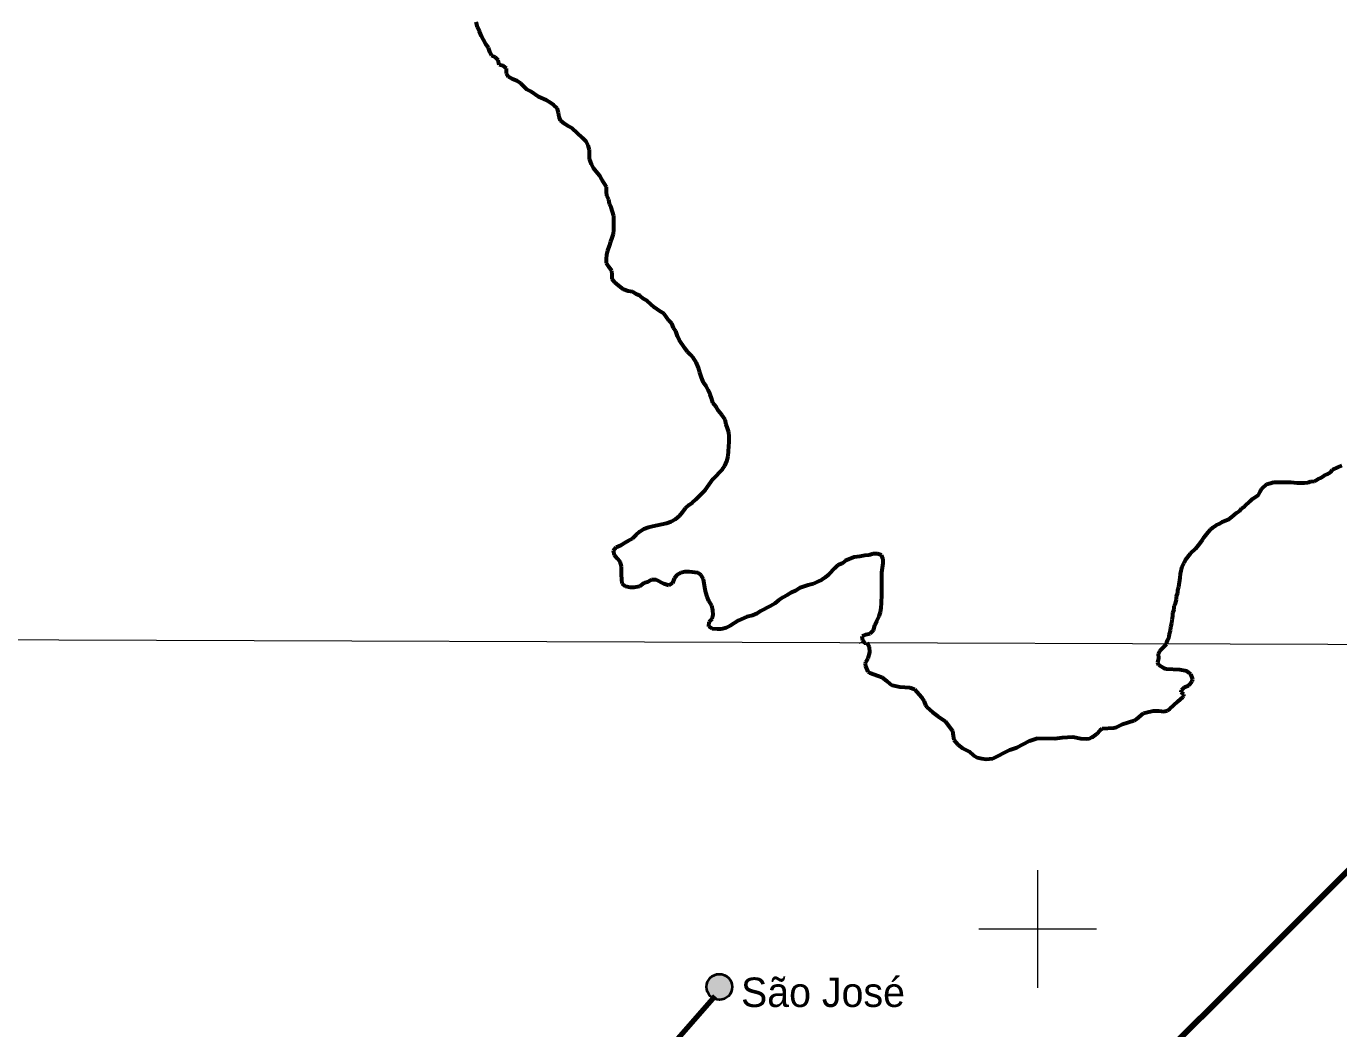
# Model space of a CAD drawing. Extents: x 553962 to 842807, y 8883888 to 9032388.
# Drawn here: x 632802 to 655119, y 8998304 to 9015346 of the extents above; entities that cross this region are included whole.
import ezdxf

# ---------------------------------------------------------------- set-up
doc = ezdxf.new("R2010")
doc.units = 0
doc.header["$LTSCALE"] = 200
doc.linetypes.add('LONG_DASH_SHORT_DASH', pattern=[9.9, 6, -1.2, 1.5, -1.2])
for name, color, linetype, lineweight in [('1', 7, 'Continuous', 13), ('2', 7, 'Continuous', 13), ('28', 7, 'Continuous', 40), ('41', 7, 'Continuous', 40), ('7', 7, 'LONG_DASH_SHORT_DASH', 60), ('9', 7, 'Continuous', 90)]:
    doc.layers.add(name, color=color, linetype=linetype, lineweight=lineweight)

msp = doc.modelspace()

# ---------------------------------------------------------------- hatches: boundary and pattern name
at = {"layer": '41'}
msp.add_hatch(color=256, dxfattribs=at).paths.add_polyline_path([(644806.7, 8999014.8, 1), (644369.1, 8999014.8, 1)])

# ---------------------------------------------------------------- linework, layer by layer
at = {"layer": '1'}
msp.add_lwpolyline([(565303.2, 9005146.6), (664889.8, 9004806.7), (719872.1, 9004543.9), (790635.8, 9004109)], dxfattribs=at)
at = {"layer": '2'}
for p, q in [((650000, 8999000), (650000, 9001000)), ((649000, 9000000), (651000, 9000000))]:
    msp.add_line(p, q, dxfattribs=at)
at = {"layer": '28', "lineweight": 80}
msp.add_lwpolyline([(639353.6, 8991465.8), (641358.6, 8995245), (644516, 8998855.8)], dxfattribs=at)
at = {"layer": '28', "lineweight": 13}
for points in [[(646965.9, 9004860.1), (647054.2, 9004901.6), (647053.5, 9004901.6), (647052.8, 9004897.4), (647051.4, 9004891.8), (647051.4, 9004880.6), (647051.4, 9004873.6), (647051.4, 9004869.4), (647051.4, 9004865.2), (647051.4, 9004859.6), (647052.1, 9004852.6), (647052.1, 9004847), (647052.1, 9004842.8), (647052.1, 9004842.1), (647052.1, 9004841.4), (647052.1, 9004840.7), (647052.8, 9004840.7), (647053.5, 9004840.7), (647057.7, 9004841.4), (647061.9, 9004842.1), (647068.9, 9004842.8), (647077.3, 9004843.5), (647085.7, 9004847.7), (647091.3, 9004849.1), (647099.7, 9004853.3), (647109.5, 9004854), (647116.5, 9004858.2), (647123.5, 9004862.4), (647124.9, 9004863.8), (647124.9, 9004868), (647124.9, 9004869.4), (647124.9, 9004870.8), (647124.9, 9004871.5), (647124.9, 9004872.9), (647124.9, 9004874.3), (647124.9, 9004875), (647124.9, 9004875.7), (647124.2, 9004875), (647122.8, 9004873.6), (647122.1, 9004865.2), (647120.7, 9004858.2), (647120, 9004854), (647120, 9004854.7), (647120, 9004855.4), (647120, 9004859.6), (647120, 9004861), (647121.4, 9004862.4), (647122.1, 9004866.6), (647122.1, 9004870.8), (647122.8, 9004876.4), (647122.8, 9004877.8), (647123.5, 9004877.8), (647124.2, 9004877.8), (647124.9, 9004877.8), (647125.6, 9004877.8)], [(647125.6, 9004877.8), (647126.3, 9004877.8), (647125.6, 9004877.8), (647126.3, 9004877.8)]]:
    msp.add_spline(points, degree=3, dxfattribs=at)
at = {"layer": '41'}
msp.add_circle((644587.9, 8999014.8), 218.8, dxfattribs=at)
at = {"layer": '7'}
for points in [[(642587.9, 9012738.2), (642555, 9012803.3), (642491.9, 9012875.8), (642449, 9012935.9), (642411, 9013003.5), (642378, 9013091.2), (642377.5, 9013241.9), (642359.6, 9013319.6), (642321.7, 9013387.2), (642261.2, 9013447.2), (642084.7, 9013614.7), (642014.2, 9013649.5), (641953.8, 9013686.9), (641888.2, 9013741.9), (641865.4, 9013807), (641855.1, 9013874.8), (641829.7, 9013952.5), (641771.7, 9014002.5), (641713.8, 9014044.9), (641640.8, 9014087.2), (641512.4, 9014146.9), (641383.9, 9014239.3), (641316, 9014271.6), (641260.5, 9014321.6), (641210.1, 9014371.6), (641144.6, 9014416.5), (641071.7, 9014443.8), (641003.7, 9014483.7), (640965.8, 9014543.8), (640965.5, 9014626.6), (640912.5, 9014674.1), (640844.6, 9014691.4), (640824.2, 9014771.6), (640776.3, 9014821.6), (640713.4, 9014849), (640683, 9014911.6), (640660.2, 9014976.8), (640614.7, 9015039.3), (640579.2, 9015117), (640541.3, 9015177.1), (640508.4, 9015254.8), (640472.9, 9015332.5), (640455.1, 9015415.2)], [(642956.5, 9010871.9), (642875.9, 9010931.8), (642812.9, 9010989.2), (642767.5, 9011046.8), (642764.7, 9011117.1), (642756.9, 9011189.8), (642714, 9011252.4), (642671, 9011320), (642668.2, 9011392.8), (642675.5, 9011460.6), (642692.8, 9011531), (642720.2, 9011611.5), (642740, 9011684.4), (642767.4, 9011749.8), (642787.2, 9011815.1), (642792, 9011885.4), (642791.1, 9012118.9), (642768.3, 9012191.6), (642750.4, 9012266.9), (642720, 9012329.5), (642709.7, 9012402.3), (642674.3, 9012462.4), (642669, 9012537.7), (642668.7, 9012615.5), (642587.9, 9012738.2)], [(642909.8, 9006525.4), (642972.5, 9006563.4), (643042.7, 9006603.9), (643110.4, 9006636.8), (643173, 9006699.9), (643233.1, 9006755.4), (643300.8, 9006800.9), (643383.6, 9006828.9), (643451.3, 9006846.8), (643689.8, 9006898), (643767.6, 9006926), (643840.3, 9006969), (643907.9, 9007024.6), (643960.5, 9007085.1), (644013, 9007153.1), (644073.1, 9007208.6), (644128.2, 9007249), (644188.3, 9007299.5), (644348.5, 9007460.9), (644480.9, 9007652.3), (644638.6, 9007816.2), (644681, 9007874.2), (644715.9, 9007949.6), (644735.7, 9008040.1), (644740.4, 9008123), (644752.4, 9008281.2), (644752, 9008371.6), (644749.2, 9008446.9), (644726.4, 9008512.1), (644706.1, 9008577.3), (644685.6, 9008662.5), (644630.1, 9008742.6), (644574.6, 9008810.2), (644531.6, 9008875.3), (644478.6, 9008945.3), (644453.2, 9009020.6), (644432.8, 9009088.2), (644394.9, 9009160.9), (644364.5, 9009226), (644319, 9009288.6), (644283.6, 9009373.8), (644253.1, 9009461.5), (644230.2, 9009539.3), (644192.1, 9009634.5), (644149.2, 9009702.1), (644098.7, 9009762.2), (644045.8, 9009812.1), (643997.8, 9009874.7), (643906.8, 9010017.4), (643876.5, 9010080), (643846, 9010160.2), (643810.6, 9010220.3), (643780.2, 9010290.5), (643729.8, 9010343), (643646.4, 9010458.1), (643563.3, 9010510.5), (643485.3, 9010562.9), (643417.2, 9010627.8), (643364.3, 9010672.8), (643296.3, 9010710.2), (643238.3, 9010762.6), (643170.4, 9010790), (643112.5, 9010829.9), (643034.5, 9010844.6), (642956.5, 9010871.9)], [(653752.9, 9007379.9), (653775.3, 9007427.7), (653812.8, 9007483.1), (653897.9, 9007561.2), (653958.1, 9007576.6), (654010.8, 9007596.9), (654166.4, 9007597.6), (654236.8, 9007595.4), (654307.1, 9007595.7), (654410.1, 9007586.1), (654535.6, 9007586.7), (654593.4, 9007589.5), (654641, 9007607.2), (654708.8, 9007615.1), (654761.4, 9007647.9), (654816.6, 9007668.3), (654871.7, 9007706.2), (654924.3, 9007729), (654976.9, 9007766.9), (655011.9, 9007802.2), (655109.7, 9007852.8), (655172.4, 9007878.2)], [(652189.6, 9004842.3), (652192.9, 9004859.9), (652210.3, 9004905.2), (652237.7, 9004965.5), (652240, 9005018.3), (652259.9, 9005071.1), (652264.7, 9005133.8), (652282, 9005196.7), (652289.3, 9005257), (652299.1, 9005319.8), (652298.9, 9005370), (652318.8, 9005430.3), (652321.1, 9005485.6), (652341, 9005540.9), (652358.3, 9005598.7), (652363.2, 9005654), (652380.5, 9005711.8), (652382.8, 9005759.5), (652402.7, 9005814.8), (652424.7, 9005970.6), (652429.5, 9006038.4), (652459.2, 9006164), (652491.6, 9006224.4), (652511.5, 9006274.7), (652599, 9006380.6), (652686.6, 9006466.3), (652759.1, 9006554.5), (652801.5, 9006612.4), (652831.5, 9006660.3), (652899, 9006745.9), (652939, 9006788.8), (652979, 9006824.1), (653036.6, 9006862), (653084.3, 9006887.3), (653139.4, 9006922.7), (653194.6, 9006943.1), (653249.7, 9006968.4), (653302.3, 9007006.3), (653379.9, 9007074.4), (653432.5, 9007099.8), (653465, 9007145.1), (653520.1, 9007188), (653615.2, 9007271.3), (653652.7, 9007314.1), (653697.8, 9007339.5), (653752.9, 9007379.9)], [(644220.5, 9006056.8), (644074.8, 9006071.2), (644001.9, 9006068.3), (643934.1, 9006053), (643864, 9006012.5), (643821.4, 9005959.6), (643789.1, 9005879.1), (643726.4, 9005838.6), (643645.9, 9005865.8), (643512.5, 9005935.6), (643434.6, 9005937.7), (643374.4, 9005902.3), (643301.7, 9005876.9), (643231.5, 9005821.3), (643141.2, 9005805.8), (643070.8, 9005805.5), (642992.8, 9005822.7), (642932.4, 9005870.2), (642927.1, 9005938), (642924.3, 9006023.3), (642924, 9006093.6), (642921.2, 9006161.4), (642900.9, 9006239.2), (642847.9, 9006296.7), (642805, 9006354.2), (642787.1, 9006434.5), (642834.6, 9006492.5), (642909.8, 9006525.4)], [(647062.3, 9004859.8), (647025.9, 9004904.3), (647013.1, 9004977.1), (647078.3, 9005005), (647151.1, 9005022.9), (647211.2, 9005080.9), (647230.9, 9005163.9), (647263.3, 9005239.3), (647305.7, 9005314.9), (647325.6, 9005382.8), (647340.4, 9005460.7), (647345.1, 9005536), (647349.6, 9005686.7), (647348.2, 9006058.2), (647370.2, 9006219), (647374.9, 9006286.8), (647347, 9006357), (647279.1, 9006376.8), (647201.3, 9006376.5), (647136, 9006353.6), (647063.2, 9006350.7), (646977.9, 9006332.8), (646882.5, 9006322.3), (646794.7, 9006286.8), (646729.5, 9006256.3), (646676.9, 9006213.4), (646604.1, 9006183), (646549, 9006135), (646446.5, 9006026.6), (646386.3, 9005976.1), (646331.2, 9005935.7), (646266, 9005907.8), (646190.8, 9005864.7), (646098, 9005846.7), (645962.5, 9005800.9), (645879.8, 9005750.3), (645814.5, 9005722.4), (645739.3, 9005674.4), (645666.7, 9005633.9), (645599, 9005588.4), (645528.9, 9005532.8), (645448.7, 9005484.8), (645288.2, 9005403.7), (645230.5, 9005363.3), (645150.3, 9005327.8), (645057.4, 9005307.2), (644911.9, 9005243.8), (644769.1, 9005152.8), (644701.4, 9005117.3), (644621.1, 9005096.9), (644548.2, 9005094), (644465.3, 9005103.7), (644409.8, 9005143.6), (644412.1, 9005221.5), (644464.7, 9005269.4), (644479.5, 9005342.3), (644479.2, 9005417.6), (644458.8, 9005497.9), (644408.2, 9005575.5), (644377.8, 9005648.2), (644360, 9005720.9), (644342.1, 9005803.7), (644318.9, 9005944.2), (644281, 9006014.3), (644220.5, 9006056.8)], [(647102.1, 9004868.2), (647133.8, 9004797.4), (647139.7, 9004697.7), (647112.7, 9004599.3), (647071.4, 9004533.6), (647065.5, 9004510.9), (647070.2, 9004465.4), (647114.8, 9004372.7), (647145.9, 9004353.5), (647287.9, 9004301.4)], [(652571.6, 9004354.9), (652533.9, 9004385), (652418.7, 9004407.8), (652184.9, 9004417.3), (652149.2, 9004427), (652060, 9004486.6), (652040.8, 9004529.2), (652062.1, 9004603.4), (652057, 9004679.8), (652075.5, 9004729.8), (652189.6, 9004842.3)], [(647287.9, 9004301.4), (647349.8, 9004278.7), (647428.9, 9004220), (647491, 9004161.7), (647523.9, 9004147.1), (647653.6, 9004116.9), (647828.8, 9004104.7), (647906.2, 9004077.1), (648025, 9003938.3), (648068.8, 9003867.8), (648090.9, 9003802.8), (648115.2, 9003770.7), (648211.5, 9003685.2), (648303.2, 9003619.5)], [(651845, 9003677.6), (651965, 9003709.1), (652060.1, 9003710.6), (652150.3, 9003698.2), (652205.6, 9003715.7), (652249.3, 9003739.3), (652381.3, 9003869), (652475, 9003944), (652487.1, 9003963.6), (652485.6, 9003982.9), (652440.3, 9004026.7), (652444.4, 9004062), (652495.8, 9004109.5), (652561.9, 9004140.7), (652594.2, 9004165.5), (652627.3, 9004213.1), (652637.1, 9004247.3), (652602.1, 9004330.6), (652571.6, 9004354.9)], [(648303.2, 9003619.5), (648427.5, 9003530.4), (648554.2, 9003368.9), (648558.1, 9003321.1)], [(650919.9, 9003259.5), (650935.6, 9003267.1), (651004.3, 9003314.6), (651061.8, 9003378.1), (651097.3, 9003405.6), (651296.7, 9003420), (651339.5, 9003432.8), (651440.7, 9003482.2), (651638.4, 9003546.2), (651687.3, 9003573.8), (651801.8, 9003666.3), (651845, 9003677.6)], [(648558.1, 9003321.1), (648561.3, 9003280.6), (648575.3, 9003215.5), (648643.2, 9003134.5), (648724.5, 9003072), (648834.8, 9003014.8), (648910.7, 9002950.7), (648970.7, 9002913.9), (649048, 9002899.4)], [(649048, 9002899.4), (649123.4, 9002885.3), (649239.3, 9002899.3), (649525.4, 9003042.3), (649646, 9003087.1)], [(649646, 9003087.1), (649861.2, 9003200.6), (649998, 9003241.4), (650289.5, 9003235), (650416.3, 9003253.8), (650598.9, 9003267.9), (650731.6, 9003237.8), (650826.9, 9003233.9), (650879.7, 9003240.2), (650919.9, 9003259.5)]]:
    msp.add_lwpolyline(points, dxfattribs=at)
at = {"layer": '9'}
msp.add_lwpolyline([(635350.7, 8977923.9), (636116.8, 8981777.4), (642228, 8989744.8), (647160.3, 8990514), (649828, 8995545.6), (655722.5, 9001435.5), (661506.7, 9009120.3)], dxfattribs=at)

# ---------------------------------------------------------------- texts
at = {"layer": '41'}
msp.add_text('São José', height=500, dxfattribs=at).set_placement((644955.9, 8998673.8))

doc.saveas('drawing.dxf')
